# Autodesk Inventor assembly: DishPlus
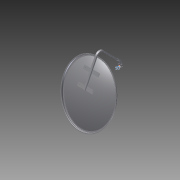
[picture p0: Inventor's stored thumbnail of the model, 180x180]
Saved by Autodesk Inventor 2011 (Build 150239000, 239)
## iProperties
Created: 2014-11
Part Number: DishPlus
Document SubType Name: Assembly
Designer: Evgeny
Author: Evgeny
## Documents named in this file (3)
- D:\Autodesk Invertor 2011\Projects2014\Antenna\UVE2.1\DishPlus.iam
- D:\Autodesk Invertor 2011\Projects2014\Antenna\UVE2.1\DishCron.ipt
- D:\Autodesk Invertor 2011\Projects2014\Antenna\UVE2.1\DishNTV20.ipt
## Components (2 placed, 2 different names)
1. DishCron:1 — Заподлицо:1, Совмещение:1, Вставка:1, Совмещение:2
2. DishNTV20:1 — Вставка:1, Совмещение:2
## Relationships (4: Mate 2, Flush 1, Insert 1)
- Заподлицо:1 [Flush]: DishCron:1
- Совмещение:1 [Mate]: DishCron:1
- Вставка:1 [Insert]: DishCron:1 ↔ DishNTV20:1
- Совмещение:2 [Mate]: DishCron:1 ↔ DishNTV20:1
